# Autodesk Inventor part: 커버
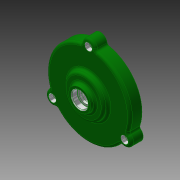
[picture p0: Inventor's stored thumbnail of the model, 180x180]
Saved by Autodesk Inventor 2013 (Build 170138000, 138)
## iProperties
Created: 2015-11
Part Number: 커버
Document SubType Name: 모델링
Designer: mdu
Material: 알루미늄 6061
Density: 2.71 g/cm^3
Mass: 213.955 g
Surface Area: 281.76 cm^2
Volume: 78.9502 cm^3
변환 표준: STEP AP214IS
파일 이름: C:\Users\SeoGD\Desktop\?쒗뿕\而ㅻ쾭-1.stp
전처리기: Build: 253, Release: 2010 SP1 - Date: Wed 07/29/2009
전송 단위: 밀리미터
불확실성: 0.01
Author: mdu
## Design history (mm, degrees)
sketch "스케치1"
  geometry: L1 (0, 0)-(0, 26); L2 (52, 0)-(52, 15); L3 (52, 15)-(25, 15); L4 (25, 15)-(25, 21); L5 (25, 21)-(15, 21); L6 (15, 21)-(13.66, 26); L7 (13.66, 26)-(10, 26); L8 (52, 0)-(45, 0); L9 (45, 0)-(45, 10); L10 (45, 10)-(14.5, 10); L11 (14.5, 10)-(13.266, 3); L12 (13.266, 3)-(11, 3); L13 (11, 3)-(11, 16); L14 (11, 16)-(7.5, 16); L15 (7.5, 16)-(7.5, 19); L16 (7.5, 19)-(10, 19); L17 (10, 19)-(10, 26)
  constraints: 34 end point, 10 parallel, 2 perpendicular, 2 point on line, 1 vertical
  dimensions: "d11" = 104 diameter of L2 L1; "d12" = 22 diameter of L13 L1; "d13" = 90 diameter of L9 L1; "d14" = 15 distance between parallel lines of L3 L8; "d15" = 10 distance between parallel lines of L8 L10; "d16" = 29 diameter of L10.end L1; "d17" = 100 deg angle of L11 L10; "d18" = 7 distance between parallel lines of L12 L10; "d19" = 13 distance between parallel lines of L14 L12; "d20" = 3 distance between parallel lines of L16 L14; "d21" = 15 diameter of L15 L1; "d22" = 20 diameter of L17 L1; "d23" = 30 diameter of L5.end L1; "d24" = 6 distance between parallel lines of L5 L3; "d25" = 50 diameter of L4 L1; "d26" = 105 deg angle of L5 L6; "d50" = 26 distance of L1.start L1.end
revolve "회전1" sketch "스케치1" stored, may be unused: angle "d27" = 90 deg
sketch "스케치2" dims "d29" = 104
  geometry: A1 r 8.5 centre (0, 52) between (8.472, 51.305) and (-8.472, 51.305); A2 r 52 centre (0, 0) between (-8.472, 51.305) and (8.472, 51.305) reference; 2 further points
  constraints: 4 point on circle, 2 vertical alignment, 1 centre point, 1 coincident, 2 other
  dimensions: "d28" = 17 diameter of A1
extrude "돌출1" join sketch "스케치2" stored distance "d30" = 10; taper "d31" = 0 deg
fillet "모깎기3" dims "d32" = 3
fillet "모깎기4" dims "d45" = 3, "d46" = 0.2
chamfer "모따기1" distance "d47" = 1; stored, may be unused: second distance "d48" = 2, angle "d49" = 45 deg
hole "구멍2" diameter "d38" = 5.5; stored, may be unused: countersink angle "d42" = 90 deg, drill point angle "d44" = 118 deg; dims "d39" = 6, "d40" = 9.5, "d41" = 5.4, "d43" = 8, "d54" = 10, "d55" = 10
node "솔리드1"
node "솔리드 본체"
node "곡면 본체"
pattern_circular "원형 패턴1" dims angle "d34" = 360 deg
pattern_circular "원형 패턴2" dims angle "d52" = 360 deg
node "솔리드2"
